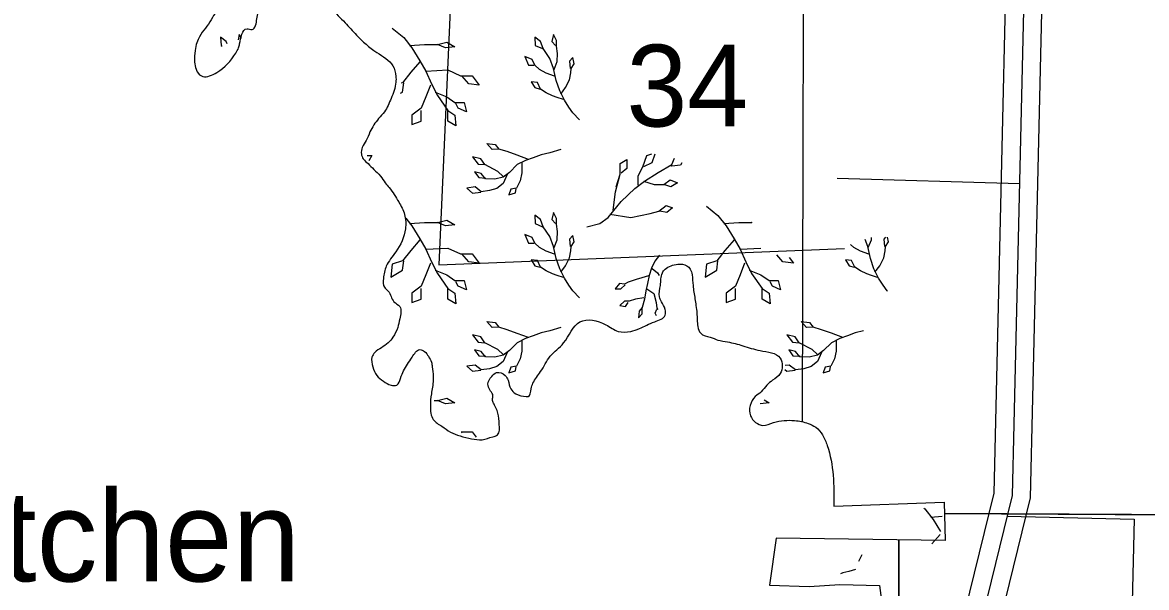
# Model space of a CAD drawing. Extents: x 380424 to 701066, y 1117407 to 1412949.
# Drawn here: x 527202 to 533390, y 1267730 to 1270841 of the extents above; entities that cross this region are included whole.
import ezdxf

# ---------------------------------------------------------------- set-up
doc = ezdxf.new("R2010")
doc.units = 0
for name, color, linetype in [('Bay Text', 7, 'Continuous'), ('Cities Incorporated Area', 7, 'Continuous'), ('Local Roads Paved', 7, 'Continuous'), ('Mangroves', 7, 'Continuous'), ('Narrow Canals', 7, 'Continuous'), ('Section Lines', 7, 'Continuous'), ('Section Numbers', 7, 'Continuous'), ('Township  and Range lines', 7, 'Continuous'), ('US Route Divided Highway Outline and Fill', 7, 'Continuous'), ('US Routes Highway Center Lines', 7, 'Continuous')]:
    doc.layers.add(name, color=color, linetype=linetype)

msp = doc.modelspace()

# ---------------------------------------------------------------- linework, layer by layer
at = {"layer": 'Cities Incorporated Area'}
msp.add_lwpolyline([(531669.4, 1268177.4), (532276.1, 1268200.5), (532281.3, 1267989.5), (531351.3, 1268001.1), (531314.4, 1267742.7), (531532.4, 1267736.3), (531701.2, 1267746.9), (531920.3, 1267742), (531939.2, 1267604.3)], dxfattribs=at)
for points in [[(528561.9, 1271631.6), (528516.7, 1271528.1), (528510.1, 1271481), (528503.4, 1271416.4), (528487.8, 1271358.5), (528476.7, 1271264.8), (528434.4, 1271157.8), (528387.6, 1271050.8), (528327.4, 1270968.4), (528309.6, 1270937.2), (528262.8, 1270890.4), (528233.8, 1270843.5), (528169.2, 1270747.7), (528196, 1270542.6), (528271.7, 1270564.9), (528376.4, 1270671.9), (528392, 1270700.9), (528397.7, 1270723.3), (528438.8, 1270805.7), (528466.3, 1270802.5), (528492.7, 1270860.5), (528501.2, 1270897), (528519, 1270937.2), (528490.1, 1270981.7), (528545.5, 1271066.4), (528550.7, 1271203.6), (528577.1, 1271340.8), (528603.5, 1271414.6), (528624.6, 1271478), (528651, 1271557.1), (528682.7, 1271636.3), (528746, 1271694.3), (528798.8, 1271720.7), (528862.1, 1271747.1), (528909.6, 1271741.8), (528941.2, 1271726), (528972.9, 1271699.6), (528999.3, 1271673.2), (529015.1, 1271652.1), (529030.9, 1271620.4), (529041.5, 1271583.5), (529046.8, 1271541.3), (529030.9, 1271472.7), (529036.2, 1271430.5), (529062.6, 1271398.8), (529083.7, 1271398.8), (529099.5, 1271409.4), (529141.8, 1271425.2), (529199.8, 1271419.9), (529242, 1271398.8), (529263.1, 1271361.9), (529263.1, 1271309.1), (529252.6, 1271266.9), (529220.9, 1271229.9), (529178.7, 1271214.1), (529120.7, 1271187.7), (529052.1, 1271171.9), (528999.3, 1271156.1), (528957.1, 1271150.8), (528909.6, 1271140.2), (528867.4, 1271119.1), (528862.1, 1271082.2), (528856.8, 1271055.8), (528862.1, 1271003), (528883.2, 1270950.3), (528904.3, 1270918.6), (528978.2, 1270839.4), (529041.5, 1270770.8), (529152.3, 1270675.9), (529242, 1270602), (529257.9, 1270543.9), (529257.9, 1270512.3), (529231.5, 1270422.6), (529194.5, 1270348.7), (529162.9, 1270311.7), (529115.4, 1270237.9), (529094.3, 1270190.4), (529073.2, 1270153.4), (529067.9, 1270116.5), (529078.4, 1270090.1), (529104.8, 1270063.7), (529136.5, 1270032.1), (529173.4, 1269995.1), (529199.8, 1269958.2), (529220.9, 1269931.8), (529273.7, 1269852.6), (529305.4, 1269784), (529310.6, 1269704.9), (529257.9, 1269578.2), (529205.1, 1269499.1), (529189.3, 1269430.5), (529194.5, 1269383), (529215.6, 1269361.9), (529247.3, 1269303.8), (529279, 1269277.4), (529279, 1269208.8), (529268.4, 1269161.3)], [(529268.4, 1269161.3), (529242, 1269108.6), (529215.6, 1269076.9), (529178.7, 1269050.5), (529141.8, 1269024.1), (529125.9, 1268997.8), (529131.2, 1268945), (529152.3, 1268897.5), (529189.3, 1268865.8), (529231.5, 1268844.7), (529263.1, 1268844.7), (529284.2, 1268881.7), (529300.1, 1268923.9), (529347.6, 1268997.8), (529389.8, 1269040), (529416.2, 1269029.4), (529437.3, 1269003), (529453.1, 1268971.4), (529458.4, 1268945), (529463.7, 1268892.2), (529463.7, 1268871.1), (529453.1, 1268797.2), (529447.8, 1268728.6), (529463.7, 1268654.8), (529511.2, 1268617.8), (529558.6, 1268586.2), (529611.4, 1268565), (529674.7, 1268549.2), (529732.8, 1268543.9), (529790.8, 1268559.8), (529817.2, 1268570.3), (529827.8, 1268596.7), (529827.8, 1268612.5), (529822.5, 1268675.9), (529801.4, 1268733.9), (529790.8, 1268755), (529790.8, 1268776.1), (529790.8, 1268792), (529775, 1268818.3), (529764.5, 1268850), (529785.6, 1268892.2), (529811.9, 1268913.3), (529859.4, 1268897.5), (529875.3, 1268871.1), (529891.1, 1268823.6), (529917.5, 1268797.2), (529975.5, 1268781.4), (529986.1, 1268781.4), (530001.9, 1268823.6), (530012.5, 1268855.3), (530054.7, 1268918.6), (530107.5, 1269003), (530181.3, 1269076.9), (530271, 1269193), (530413.5, 1269177.2), (530482.1, 1269140.3), (530550.7, 1269140.3), (530598.2, 1269156.1), (530682.6, 1269193), (530740.7, 1269230), (530740.7, 1269261.6), (530719.6, 1269303.8), (530709, 1269330.2), (530714.3, 1269393.6), (530724.9, 1269462.2), (530740.7, 1269483.3), (530809.3, 1269509.6), (530835.7, 1269509.6), (530877.9, 1269483.3), (530888.4, 1269451.6), (530893.7, 1269393.6), (530904.3, 1269319.7), (530909.6, 1269282.7), (530914.8, 1269240.5), (530920.1, 1269166.6), (530935.9, 1269129.7), (530988.7, 1269108.6), (531030.9, 1269092.8), (531083.7, 1269082.2), (531168.1, 1269061.1), (531263.1, 1269034.7), (531373.9, 1268992.5), (531373.9, 1268908.1), (531331.7, 1268871.1), (531300.1, 1268844.7), (531268.4, 1268807.8), (531236.7, 1268781.4), (531210.3, 1268675.9), (531278.9, 1268623.1), (531337, 1268638.9), (531395, 1268649.5), (531453.1, 1268649.5), (531527, 1268633.7), (531569.2, 1268612.6), (531606.1, 1268570.3), (531632.5, 1268512.3), (531669.4, 1268177.4)]]:
    msp.add_spline(points, degree=3, dxfattribs=at)
at = {"layer": 'Local Roads Paved'}
for points in [[(532690.8, 1269952.8), (531686.4, 1269981.6)], [(532622.8, 1268122.6), (533322.5, 1268107.2), (533258.3, 1265433.1), (531964, 1265473.3), (529688.8, 1265494.1), (529699.2, 1264168), (531829.1, 1264150.9)]]:
    msp.add_lwpolyline(points, dxfattribs=at)
at = {"layer": 'Mangroves'}
msp.add_line((530471.3, 1269935.4), (530493.5, 1270006.2), dxfattribs=at)
for points in [[(528395.6, 1270773.8), (528389, 1270745)], [(528407.7, 1270751.8), (528395.6, 1270773.8)], [(529237.2, 1270809.2), (529301.1, 1270758.1)], [(530128.5, 1270582.1), (530145.7, 1270625.1), (530148.5, 1270670.8), (530142.8, 1270710.9), (530142.8, 1270742.3), (530125.6, 1270773.8), (530117.1, 1270736.6), (530137.1, 1270713.7)], [(528324.1, 1270736.6), (528292.7, 1270759.5)], [(528292.7, 1270759.5), (528295.5, 1270713.7)], [(528295.5, 1270713.7), (528301.3, 1270711.2)], [(528329.2, 1270722.4), (528324.1, 1270736.6)], [(529301.1, 1270758.1), (529345.8, 1270700.6)], [(529333, 1270713.4), (529416.1, 1270719.8), (529486.4, 1270719.8), (529537.5, 1270732.5), (529582.2, 1270707), (529531.1, 1270700.6), (529486.4, 1270719.8)], [(530054.1, 1270736.6), (530022.7, 1270759.5)], [(530022.7, 1270759.5), (530025.5, 1270713.7)], [(530025.5, 1270713.7), (530065.6, 1270696.6)], [(530068.4, 1270696.6), (530054.1, 1270736.6)], [(529345.8, 1270700.6), (529390.5, 1270630.3)], [(530131.4, 1270545), (530085.6, 1270562.1), (530048.4, 1270582.1), (530022.7, 1270605), (530008.4, 1270636.5), (529968.3, 1270653.7), (529988.3, 1270605), (530019.8, 1270605)], [(530105.6, 1270642.2), (530068.4, 1270696.6)], [(530165.5, 1270446.9), (530191.4, 1270482), (530214.3, 1270524.9), (530221, 1270563.7), (530222.9, 1270587.9), (530240.1, 1270613.6), (530231.5, 1270647.9), (530214.3, 1270627.9), (530217.2, 1270587.9)], [(529390.5, 1270623.9), (529339.4, 1270566.4)], [(529390.5, 1270630.3), (529422.5, 1270572.8)], [(530125.6, 1270587.9), (530105.6, 1270642.2)], [(530139.9, 1270522.1), (530125.6, 1270587.9)], [(529339.4, 1270566.4), (529294.7, 1270508.9)], [(529422.5, 1270572.8), (529543.9, 1270579.2), (529614.2, 1270547.2), (529678, 1270547.2), (529716.4, 1270496.1), (529658.9, 1270502.5), (529620.5, 1270547.2)], [(529422.5, 1270572.8), (529454.4, 1270502.5)], [(529294.7, 1270508.9), (529287.5, 1270506.5)], [(529294.7, 1270457.8), (529301.1, 1270508.9)], [(529448, 1270496.1), (529422.5, 1270432.2), (529396.9, 1270368.3), (529345.8, 1270330), (529345.8, 1270278.9), (529396.9, 1270298), (529396.9, 1270355.6)], [(529454.4, 1270502.5), (529486.4, 1270438.6)], [(530180, 1270416.2), (530145.7, 1270427.7), (530119.9, 1270436.3), (530085.6, 1270453.4), (530054.1, 1270473.5), (530037, 1270510.6), (530002.7, 1270513.5), (530022.7, 1270482), (530051.3, 1270473.5)], [(530160, 1270464.9), (530139.9, 1270522.1)], [(530185.7, 1270413.4), (530160, 1270464.9)], [(529283.6, 1270451.1), (529294.7, 1270457.8)], [(529473.6, 1270457.8), (529537.5, 1270432.2), (529582.2, 1270400.3), (529633.3, 1270400.3), (529646.1, 1270349.2), (529601.4, 1270368.3), (529588.6, 1270393.9)], [(529486.4, 1270438.6), (529543.9, 1270355.6)], [(530210.7, 1270374.1), (530185.7, 1270413.4)], [(529543.9, 1270355.6), (529582.2, 1270330)], [(529543.9, 1270298), (529543.9, 1270355.6)], [(530231.8, 1270344), (530210.7, 1270374.1)], [(530268.7, 1270304.7), (530231.8, 1270344)], [(529588.6, 1270272.5), (529543.9, 1270298)], [(529582.2, 1270330), (529588.6, 1270272.5)], [(529988.3, 1270086.7), (529925.4, 1270109.5), (529871.1, 1270129.6), (529825.3, 1270143.9), (529788.1, 1270141), (529759.5, 1270175.3), (529805.3, 1270169.6), (529825.3, 1270143.9)], [(529099, 1270108), (529126.4, 1270108)], [(529126.4, 1270108), (529109.3, 1270078.6)], [(529848.2, 1269992.3), (529819.6, 1270020.9), (529748.1, 1270058.1), (529725.2, 1270089.5), (529679.4, 1270101), (529710.9, 1270060.9), (529748.1, 1270058.1)], [(530165.7, 1270141), (530105.6, 1270123.8), (530057, 1270112.4), (530014.1, 1270095.2), (529971.2, 1270080.9), (529925.4, 1270058.1), (529882.5, 1270015.2), (529848.2, 1269989.4), (529802.4, 1269978), (529750.9, 1269980.8), (529728, 1270009.4), (529690.9, 1270018), (529713.7, 1269986.5), (529753.8, 1269983.7)], [(530617.4, 1270046.1), (530639.6, 1270108)], [(530639.6, 1270108), (530666.3, 1270117.8)], [(530684.2, 1270115.2), (530666.1, 1270068.2)], [(530776.8, 1270059.3), (530792.2, 1270093.3)], [(529951.2, 1270069.5), (529951.2, 1270012.3), (529942.6, 1269969.4), (529922.6, 1269929.3), (529891.1, 1269923.6), (529879.6, 1269892.2), (529916.8, 1269903.6), (529919.7, 1269926.5)], [(530453.6, 1269807), (530466.9, 1269908.8), (530493.5, 1270006.2), (530493.5, 1270063.8), (530528.9, 1270085.9), (530528.9, 1270037.2), (530497.9, 1270010.7)], [(530590.9, 1269997.4), (530617.4, 1270046.1)], [(530666.1, 1270068.2), (530621.8, 1270046.1)], [(530701.5, 1270015.1), (530776.8, 1270059.3)], [(530776.8, 1270050.5), (530772.5, 1270054.4)], [(530825.5, 1270054.9), (530776.8, 1270050.5)], [(530832.6, 1270067.2), (530825.5, 1270054.9)], [(529871.1, 1270003.7), (529848.2, 1269955.1), (529813.9, 1269926.5), (529773.8, 1269915), (529728, 1269909.3), (529693.7, 1269935.1), (529648, 1269929.3), (529679.4, 1269900.7), (529725.2, 1269906.5)], [(530590.9, 1269944.3), (530590.9, 1269997.4)], [(530621.8, 1269966.4), (530679.4, 1269948.7), (530732.5, 1269948.7), (530767.9, 1269975.2), (530807.8, 1269957.5), (530772.3, 1269935.4), (530732.5, 1269948.7)], [(530626.3, 1269966.4), (530701.5, 1270015.1)], [(530497.9, 1269855.7), (530573.2, 1269926.5)], [(530573.2, 1269926.5), (530626.3, 1269966.4)], [(530427.1, 1269767.2), (530497.9, 1269855.7)], [(530128.5, 1269602.1), (530145.7, 1269645), (530148.5, 1269690.8), (530142.8, 1269730.9), (530142.8, 1269762.3), (530125.6, 1269793.8), (530117.1, 1269756.6), (530137.1, 1269733.7)], [(530435.9, 1269784.9), (530551, 1269767.2), (530657.3, 1269789.3), (530705.9, 1269802.6), (530745.8, 1269833.6), (530781.2, 1269820.3), (530750.2, 1269793.8), (530710.4, 1269802.6)], [(530967.2, 1269829.2), (531031.1, 1269778.1)], [(529312.2, 1269763.7), (529345.8, 1269720.6)], [(529333, 1269733.4), (529416.1, 1269739.8), (529486.4, 1269739.8), (529537.5, 1269752.5), (529582.2, 1269727), (529531.1, 1269720.6), (529486.4, 1269739.8)], [(529345.8, 1269720.6), (529390.5, 1269650.3)], [(530268.7, 1269324.7), (530231.8, 1269364), (530210.7, 1269394.1), (530185.7, 1269433.4), (530160, 1269484.9), (530139.9, 1269542.1), (530125.6, 1269607.9), (530105.6, 1269662.2), (530068.4, 1269716.6), (530054.1, 1269756.6), (530022.7, 1269779.5), (530025.5, 1269733.7), (530065.6, 1269716.6)], [(530309.8, 1269716.3), (530380.6, 1269734)], [(530380.6, 1269734), (530427.1, 1269767.2)], [(531031.1, 1269778.1), (531075.8, 1269720.6)], [(531063, 1269733.4), (531146.1, 1269739.8)], [(531075.8, 1269720.6), (531120.5, 1269650.3)], [(531146.1, 1269739.8), (531216.4, 1269739.8)], [(531216.4, 1269739.8), (531219.7, 1269740.6)], [(531219.9, 1269738.3), (531216.4, 1269739.8)], [(530131.4, 1269565), (530085.6, 1269582.1), (530048.4, 1269602.1), (530022.7, 1269625), (530008.4, 1269656.5), (529968.3, 1269673.6), (529988.4, 1269625), (530019.8, 1269625)], [(530165.5, 1269466.9), (530191.4, 1269502), (530214.3, 1269544.9), (530221, 1269583.7), (530222.9, 1269607.9), (530240.1, 1269633.6), (530231.5, 1269667.9), (530214.3, 1269647.9), (530217.2, 1269607.9)], [(531875.7, 1269645.1), (531876.5, 1269657.9)], [(531953.9, 1269659.1), (531944.3, 1269647.9)], [(531970.1, 1269633.6), (531963.9, 1269658.3)], [(529390.5, 1269643.9), (529339.4, 1269586.4)], [(529390.5, 1269650.3), (529422.5, 1269592.8)], [(529422.5, 1269592.8), (529543.9, 1269599.2), (529614.2, 1269567.2), (529678.1, 1269567.2), (529716.4, 1269516.1), (529658.9, 1269522.5), (529620.5, 1269567.2)], [(531120.5, 1269643.9), (531069.4, 1269586.4), (531024.7, 1269528.9), (530967.2, 1269509.7), (530960.8, 1269439.5), (531024.7, 1269477.8), (531031.1, 1269528.9)], [(531120.5, 1269650.3), (531152.5, 1269592.8)], [(531152.5, 1269592.8), (531266.7, 1269598.8)], [(531778.4, 1269602.2), (531760.5, 1269618.1)], [(531815.6, 1269582.1), (531778.4, 1269602.2)], [(531855.6, 1269607.9), (531841.6, 1269645.9)], [(531869.9, 1269542.1), (531855.6, 1269607.9)], [(531858.5, 1269602.2), (531875.7, 1269645.1)], [(531944.3, 1269647.9), (531947.2, 1269607.9)], [(531951, 1269583.7), (531952.9, 1269607.9)], [(531952.9, 1269607.9), (531970.1, 1269633.6)], [(529339.4, 1269586.4), (529294.7, 1269528.9)], [(529422.5, 1269592.8), (529454.4, 1269522.5)], [(530708.8, 1269560.4), (530683, 1269526)], [(531152.5, 1269592.8), (531184.4, 1269522.5)], [(531388.9, 1269522.5), (531355, 1269562)], [(531422.9, 1269547.5), (531446.4, 1269516.1)], [(531910, 1269436.3), (531875.7, 1269447.7), (531849.9, 1269456.3), (531815.6, 1269473.4), (531784.1, 1269493.5), (531767, 1269530.6), (531732.7, 1269533.5), (531752.7, 1269502), (531781.3, 1269493.5)], [(531861.4, 1269565), (531815.6, 1269582.1)], [(531890, 1269484.9), (531869.9, 1269542.1)], [(531921.4, 1269502), (531944.3, 1269544.9)], [(531944.3, 1269544.9), (531951, 1269583.7)], [(529237.2, 1269509.7), (529230.8, 1269439.4)], [(529230.8, 1269439.4), (529294.7, 1269477.8)], [(529294.7, 1269528.9), (529237.2, 1269509.7)], [(529294.7, 1269477.8), (529301.1, 1269528.9)], [(529448, 1269516.1), (529422.5, 1269452.2), (529396.9, 1269388.3), (529345.8, 1269350), (529345.8, 1269298.9), (529396.9, 1269318), (529396.9, 1269375.5)], [(529454.4, 1269522.5), (529486.4, 1269458.6)], [(529473.6, 1269477.8), (529537.5, 1269452.2), (529582.2, 1269420.3), (529633.3, 1269420.3), (529646.1, 1269369.2), (529601.4, 1269388.3), (529588.6, 1269413.9)], [(530180, 1269436.2), (530145.7, 1269447.7), (530119.9, 1269456.3), (530085.6, 1269473.4), (530054.1, 1269493.4), (530037, 1269530.6), (530002.7, 1269533.5), (530022.7, 1269502), (530051.3, 1269493.4)], [(530665.9, 1269488.9), (530651.6, 1269448.8)], [(530683, 1269526), (530665.9, 1269488.9)], [(530668.7, 1269486), (530697.3, 1269463.1)], [(531178, 1269516.1), (531152.5, 1269452.2), (531126.9, 1269388.3), (531075.8, 1269350), (531075.8, 1269298.9), (531126.9, 1269318.1), (531126.9, 1269375.6)], [(531184.4, 1269522.5), (531216.4, 1269458.6)], [(531203.6, 1269477.8), (531267.5, 1269452.2), (531312.2, 1269420.3), (531363.3, 1269420.3), (531376.1, 1269369.2), (531331.4, 1269388.3), (531318.6, 1269413.9)], [(531446.4, 1269516.1), (531388.9, 1269522.5)], [(531915.7, 1269433.4), (531890, 1269484.9)], [(531895.5, 1269466.9), (531921.4, 1269502)], [(529486.4, 1269458.6), (529543.9, 1269375.5)], [(530648.7, 1269445.9), (530611.5, 1269434.5), (530580.1, 1269425.9), (530537.2, 1269411.6), (530517.1, 1269400.2), (530488.5, 1269403), (530465.7, 1269374.4), (530497.1, 1269374.4), (530520, 1269397.3)], [(530651.6, 1269448.8), (530643, 1269403)], [(530697.3, 1269463.1), (530708.1, 1269447.7)], [(531216.4, 1269458.6), (531273.9, 1269375.6)], [(531940.7, 1269394.1), (531915.7, 1269433.4)], [(529543.9, 1269375.5), (529582.2, 1269350)], [(529543.9, 1269318), (529543.9, 1269375.5)], [(529582.2, 1269350), (529588.6, 1269292.5)], [(530634.2, 1269363.3), (530625.8, 1269317.2)], [(530643, 1269403), (530634.2, 1269363.3)], [(530640.1, 1269374.4), (530677.3, 1269348.7)], [(530677.3, 1269348.7), (530691.6, 1269300.1)], [(531273.9, 1269375.6), (531312.2, 1269350)], [(531273.9, 1269318.1), (531273.9, 1269375.6)], [(531312.2, 1269350), (531318.6, 1269292.5)], [(531961.8, 1269364), (531940.7, 1269394.1)], [(531964.1, 1269361.6), (531961.8, 1269364)], [(529588.6, 1269292.5), (529543.9, 1269318)], [(530623, 1269325.8), (530577.2, 1269317.2), (530542.9, 1269305.8), (530517.1, 1269305.8), (530491.4, 1269282.9), (530522.9, 1269277.2), (530537.2, 1269300.1)], [(530625.8, 1269317.2), (530614.4, 1269271.5)], [(530691.6, 1269300.1), (530694.5, 1269268.6)], [(531318.6, 1269292.5), (531273.9, 1269318.1)], [(530597.2, 1269251.4), (530594.4, 1269214.3)], [(530594.4, 1269214.3), (530614.4, 1269237.1)], [(530614.4, 1269271.5), (530597.2, 1269251.4)], [(530614.4, 1269237.1), (530614.4, 1269271.5)], [(530685.9, 1269240), (530694.5, 1269262.9)], [(530693.1, 1269225.7), (530685.9, 1269240)], [(530694.5, 1269268.6), (530700.5, 1269260.5)], [(529988.3, 1269106.7), (529925.4, 1269129.5), (529871.1, 1269149.6), (529825.3, 1269163.9), (529788.1, 1269161), (529759.5, 1269195.3), (529805.3, 1269189.6), (529825.3, 1269163.9)], [(531718.3, 1269106.7), (531655.4, 1269129.6), (531601.1, 1269149.6), (531555.3, 1269163.9), (531518.1, 1269161), (531489.5, 1269195.3), (531535.3, 1269189.6), (531555.3, 1269163.9)], [(529848.2, 1269012.3), (529819.6, 1269040.9), (529748.1, 1269078), (529725.2, 1269109.5), (529679.4, 1269121), (529710.9, 1269080.9), (529748.1, 1269078)], [(529971.2, 1269100.9), (529925.4, 1269078.1)], [(530014.1, 1269115.2), (529971.2, 1269100.9)], [(530057, 1269132.4), (530014.1, 1269115.2)], [(530105.6, 1269143.8), (530057, 1269132.4)], [(530165.7, 1269161), (530105.6, 1269143.8)], [(531578.2, 1269012.3), (531549.6, 1269040.9), (531478.1, 1269078.1), (531455.2, 1269109.5), (531409.4, 1269121), (531440.9, 1269080.9), (531478.1, 1269078.1)], [(531701.2, 1269100.9), (531655.4, 1269078.1)], [(531744.1, 1269115.2), (531701.2, 1269100.9)], [(531787, 1269132.4), (531744.1, 1269115.2)], [(531831.6, 1269142.9), (531787, 1269132.4)], [(529951.2, 1269089.5), (529951.2, 1269032.3), (529942.6, 1268989.4), (529922.6, 1268949.3), (529891.1, 1268943.6), (529879.6, 1268912.2), (529916.8, 1268923.6), (529919.7, 1268946.5)], [(529925.4, 1269078.1), (529882.5, 1269035.1)], [(531681.2, 1269089.5), (531681.2, 1269032.3), (531672.6, 1268989.4), (531652.5, 1268949.3), (531621.1, 1268943.6), (531609.6, 1268912.2), (531646.8, 1268923.6), (531649.7, 1268946.5)], [(531655.4, 1269078.1), (531612.5, 1269035.2)], [(529728.1, 1269029.4), (529690.9, 1269038)], [(529690.9, 1269038), (529713.8, 1269006.5)], [(529713.8, 1269006.5), (529753.8, 1269003.7)], [(529750.9, 1269000.8), (529728.1, 1269029.4)], [(529802.4, 1268998), (529750.9, 1269000.8)], [(529848.2, 1269009.4), (529802.4, 1268998)], [(529882.5, 1269035.1), (529848.2, 1269009.4)], [(529871.1, 1269023.7), (529848.2, 1268975.1)], [(531458, 1269029.4), (531420.9, 1269038)], [(531420.9, 1269038), (531443.7, 1269006.6)], [(531443.7, 1269006.6), (531483.8, 1269003.7)], [(531480.9, 1269000.8), (531458, 1269029.4)], [(531532.4, 1268998), (531480.9, 1269000.8)], [(531578.2, 1269009.4), (531532.4, 1268998)], [(531612.5, 1269035.2), (531578.2, 1269009.4)], [(531601.1, 1269023.7), (531578.2, 1268975.1)], [(529693.7, 1268955.1), (529648, 1268949.3)], [(529648, 1268949.3), (529679.4, 1268920.7)], [(529679.4, 1268920.7), (529725.2, 1268926.5)], [(529728.1, 1268929.3), (529693.7, 1268955.1)], [(529773.8, 1268935), (529728.1, 1268929.3)], [(529813.9, 1268946.5), (529773.8, 1268935)], [(529848.2, 1268975.1), (529813.9, 1268946.5)], [(531398.8, 1268930.4), (531409.4, 1268920.7)], [(531423.7, 1268955.1), (531401, 1268952.2)], [(531409.4, 1268920.7), (531455.2, 1268926.5)], [(531458, 1268929.3), (531423.7, 1268955.1)], [(531503.8, 1268935), (531458, 1268929.3)], [(531543.9, 1268946.5), (531503.8, 1268935)], [(531578.2, 1268975.1), (531543.9, 1268946.5)], [(529469.1, 1268759.8), (529486.4, 1268759.8)], [(529486.4, 1268759.8), (529537.5, 1268772.5)], [(529531.1, 1268740.6), (529486.4, 1268759.8)], [(529582.2, 1268747), (529531.1, 1268740.6)], [(529537.5, 1268772.5), (529582.2, 1268747)], [(531312.2, 1268747), (531264.1, 1268741)], [(531284.8, 1268762.6), (531312.2, 1268747)], [(529617, 1268587.2), (529678.1, 1268587.2)], [(529625, 1268582), (529620.5, 1268587.2)], [(529678.1, 1268587.2), (529700.1, 1268557.8)], [(532164, 1268167.6), (532170.3, 1268162.6)], [(532170.3, 1268162.6), (532215, 1268105.1)], [(532202.2, 1268117.8), (532266, 1268122.8)], [(532215, 1268105.1), (532256.8, 1268039.4)], [(532254.9, 1268023), (532208.6, 1267970.9)], [(531822.2, 1267910.5), (531805.1, 1267873.3)], [(531719.3, 1267810.4), (531705.4, 1267805.8)], [(531750.7, 1267819), (531719.3, 1267810.4)], [(531787.9, 1267830.4), (531750.7, 1267819)]]:
    msp.add_lwpolyline(points, dxfattribs=at)
at = {"layer": 'Narrow Canals'}
msp.add_lwpolyline([(529646.5, 1272934.5), (529495, 1269507), (531727.8, 1269596.8)], dxfattribs=at)
at = {"layer": 'Section Lines'}
for points in [[(531503.8, 1272478.4), (531505.1, 1272973), (536826.1, 1272963.6), (536735.2, 1268114.2), (532277.6, 1268137.6)], [(531503.5, 1272364.8), (531493.8, 1268642.8)], [(532277.6, 1268137.6), (536735.2, 1268114.2), (537299.9, 1268111.1), (537247, 1262765.7), (532013.4, 1262848.3), (532027.1, 1267992.7)], [(532027.1, 1267992.7), (532013.4, 1262848.3), (527608.6, 1262882.4)]]:
    msp.add_lwpolyline(points, dxfattribs=at)
at = {"layer": 'Township  and Range lines'}
msp.add_line((532277.6, 1268137.6), (536735.2, 1268114.2), dxfattribs=at)
at = {"layer": 'US Route Divided Highway Outline and Fill'}
for points in [[(531932, 1265726.6), (532551, 1268249.9), (532744.9, 1276565.5)], [(532944.9, 1276561.9), (532750.5, 1268223.5), (532124.7, 1265672.6)]]:
    msp.add_lwpolyline(points, dxfattribs=at)
at = {"layer": 'US Routes Highway Center Lines'}
msp.add_lwpolyline([(532844.9, 1276563.7), (532650.8, 1268236.7), (532028.4, 1265699.7)], dxfattribs=at)

# ---------------------------------------------------------------- texts
at = {"layer": 'Bay Text'}
msp.add_text('The Kitchen', height=500, rotation=0.00044, dxfattribs=at).set_placement((525162.4, 1267763.9))
at = {"layer": 'Section Numbers'}
msp.add_text('34', height=450, dxfattribs=at).set_placement((530527.5, 1270268.2))

doc.saveas('drawing.dxf')
